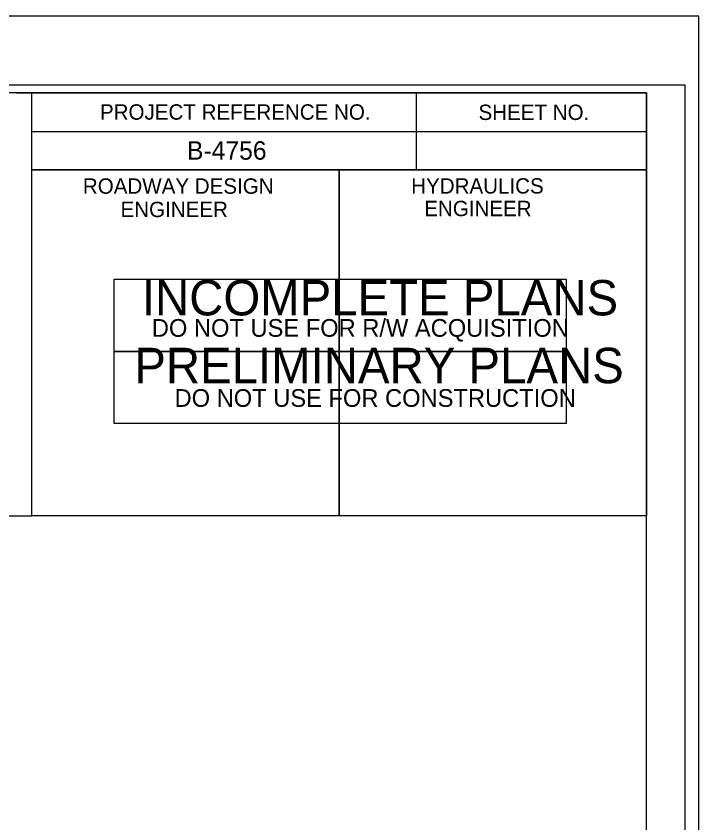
# Model space of a CAD drawing. Extents: x 2431000 to 2534000, y 645879 to 714000.
# Drawn here: x 2469872.8 to 2470094.9, y 672216.1 to 672478.6 of the extents above; entities that cross this region are included whole.
import ezdxf

# ---------------------------------------------------------------- set-up
doc = ezdxf.new("R2010")
doc.units = 0
for name, color, linetype in [('KHA_LOGO', 7, 'Continuous'), ('Prop Dimension', 7, 'Continuous'), ('Prop Shade Medium', 7, 'Continuous'), ('Prop Terminator CELL', 7, 'Continuous'), ('Sheet Clip Boundary CELL', 7, 'Continuous'), ('Sheet Cross Section CELL', 7, 'Continuous'), ('Sheet Cross Section Grid Major CELL', 7, 'Continuous'), ('Sheet Layout Profile Border Port 2', 7, 'Continuous'), ('Sheet North Arrow Point CELL', 7, 'Continuous'), ('Sheet Plan And Profile CELL', 7, 'Continuous'), ('Sheet Plan CELL', 7, 'Continuous')]:
    doc.layers.add(name, color=color, linetype=linetype)

msp = doc.modelspace()

# ---------------------------------------------------------------- linework, layer by layer
at = {"layer": 'Prop Dimension'}
msp.add_lwpolyline([(2468411.43, 671378.63), (2470094.93, 671378.63), (2470094.93, 672478.63), (2468411.43, 672478.63)], close=True, dxfattribs=at)
at = {"layer": 'Prop Shade Medium'}
msp.add_line((2470077.93, 671953.63), (2470077.93, 672316.08), dxfattribs=at)
at = {"layer": 'Prop Terminator CELL'}
msp.add_lwpolyline([(2468424.43, 671401.13), (2470090.43, 671401.13), (2470090.43, 672456.13), (2468424.43, 672456.13)], close=True, dxfattribs=at)
at = {"layer": 'Sheet Clip Boundary CELL'}
msp.add_lwpolyline([(2469777.88, 672316.08), (2469877.88, 672316.08), (2469877.88, 672453.63), (2469777.88, 672453.63)], close=True, dxfattribs=at)
at = {"layer": 'Sheet Cross Section CELL'}
for p, q in [((2469877.88, 672448.63), (2469877.93, 672448.63)), ((2469877.93, 672443.63), (2469877.88, 672443.63)), ((2469877.88, 672438.63), (2469877.93, 672438.63))]:
    msp.add_line(p, q, dxfattribs=at)
for points in [[(2469872.93, 672453.63), (2469882.93, 672453.63)], [(2469877.93, 672433.63), (2469877.88, 672433.63)], [(2469877.88, 672423.63), (2469877.93, 672423.63)], [(2469877.88, 672413.63), (2469877.93, 672413.63)], [(2469877.93, 672408.63), (2469877.88, 672408.63)], [(2469877.88, 672398.63), (2469877.93, 672398.63)], [(2469877.93, 672393.63), (2469877.88, 672393.63)], [(2469877.88, 672388.63), (2469877.93, 672388.63)], [(2469877.93, 672383.63), (2469877.88, 672383.63)], [(2469877.88, 672373.63), (2469877.93, 672373.63)], [(2469877.93, 672368.63), (2469877.88, 672368.63)], [(2469877.88, 672363.63), (2469877.93, 672363.63)], [(2469877.93, 672358.63), (2469877.88, 672358.63)], [(2469877.88, 672348.63), (2469877.93, 672348.63)], [(2469877.93, 672343.53), (2469877.88, 672343.53)], [(2469877.88, 672338.63), (2469877.93, 672338.63)], [(2469877.93, 672333.63), (2469877.88, 672333.63)], [(2469877.88, 672323.63), (2469877.93, 672323.63)]]:
    msp.add_lwpolyline(points, dxfattribs=at)
at = {"layer": 'Sheet Cross Section Grid Major CELL'}
msp.add_lwpolyline([(2469877.93, 672378.63), (2469877.88, 672378.63)], dxfattribs=at)
at = {"layer": 'Sheet Layout Profile Border Port 2'}
msp.add_lwpolyline([(2469904.76, 672369.54), (2469904.76, 672393.04), (2470051.76, 672393.04), (2470051.76, 672369.54)], close=True, dxfattribs=at)
at = {"layer": 'Sheet North Arrow Point CELL'}
for points in [[(2469877.88, 672403.63), (2469877.93, 672403.63)], [(2469877.93, 672353.63), (2469877.88, 672353.63)]]:
    msp.add_lwpolyline(points, dxfattribs=at)
at = {"layer": 'Sheet Plan And Profile CELL'}
for p, q in [((2470002.93, 672453.58), (2470002.93, 672428.58)), ((2469877.88, 672441.08), (2470077.93, 672441.08)), ((2469977.93, 672428.58), (2469977.93, 672316.13))]:
    msp.add_line(p, q, dxfattribs=at)
for points in [[(2470077.93, 672453.63), (2468577.93, 672453.63), (2468577.93, 671403.63), (2470077.93, 671403.63)], [(2469877.88, 672453.63), (2470077.93, 672453.63), (2470077.93, 672428.58), (2469877.88, 672428.58)], [(2469877.88, 672428.58), (2469977.93, 672428.58), (2469977.93, 672316.08), (2469877.88, 672316.08)], [(2469977.93, 672428.58), (2470077.93, 672428.58), (2470077.93, 672316.08), (2469977.93, 672316.08)]]:
    msp.add_lwpolyline(points, close=True, dxfattribs=at)
at = {"layer": 'Sheet Plan CELL'}
msp.add_lwpolyline([(2469904.76, 672346.04), (2469904.76, 672369.54), (2470051.76, 672369.54), (2470051.76, 672346.04)], close=True, dxfattribs=at)

# ---------------------------------------------------------------- texts
at = {"layer": 'KHA_LOGO'}
msp.add_text('B-4756', height=6, dxfattribs=at).set_placement((2469928.42, 672431.92))
at = {"layer": 'Sheet Layout Profile Border Port 2'}
for s, height, p in [('INCOMPLETE PLANS', 11.52, (2469913.72, 672381.25)), ('DO NOT USE FOR R/W ACQUISITION', 5.76, (2469916.97, 672374.3))]:
    msp.add_text(s, height=height, dxfattribs=at).set_placement(p)
at = {"layer": 'Sheet Plan And Profile CELL'}
for s, height, p in [('PROJECT REFERENCE NO.', 5.0001, (2469900.09, 672444.94)), ('SHEET NO.', 5, (2470023.24, 672444.84)), ('ROADWAY DESIGN', 5.0001, (2469894.54, 672420.84)), ('HYDRAULICS', 5, (2470001.35, 672420.89)), ('ENGINEER', 5, (2469906.79, 672413.24)), ('ENGINEER', 5, (2470005.6, 672413.54))]:
    msp.add_text(s, height=height, dxfattribs=at).set_placement(p)
at = {"layer": 'Sheet Plan CELL'}
for s, height, p in [('PRELIMINARY PLANS', 11.52, (2469911.27, 672359.2)), ('DO NOT USE FOR CONSTRUCTION', 5.76, (2469924.37, 672351.5))]:
    msp.add_text(s, height=height, dxfattribs=at).set_placement(p)

doc.saveas('drawing.dxf')
